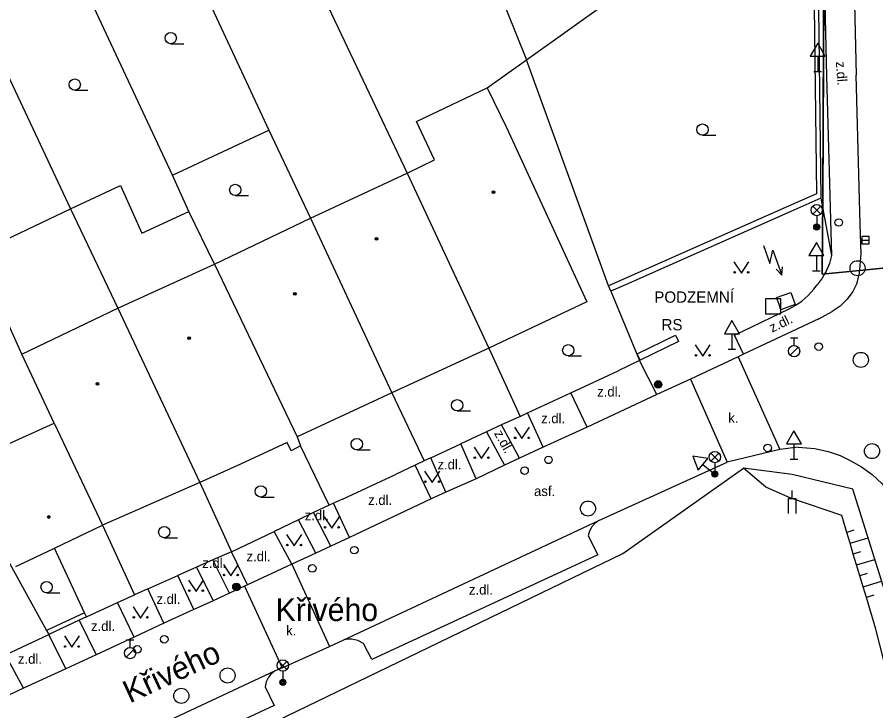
# Model space of a CAD drawing. Extents: x -598233 to -596890, y -1157848 to -1156431.
# Drawn here: x -598078.4 to -598021.4, y -1157106.7 to -1157060.7 of the extents above; entities that cross this region are included whole.
import ezdxf

# ---------------------------------------------------------------- set-up
doc = ezdxf.new("R2010")
doc.units = 0
for name, color, linetype in [('Level 10', 7, 'Continuous'), ('Level 11', 7, 'Continuous'), ('Level 14', 7, 'Continuous'), ('Level 15', 7, 'Continuous'), ('Level 24', 7, 'Continuous'), ('Level 25', 7, 'Continuous'), ('Level 26', 7, 'Continuous'), ('Level 27', 7, 'Continuous'), ('Level 28', 7, 'Continuous'), ('Level 33', 7, 'Continuous'), ('Level 34', 7, 'Continuous'), ('Level 36', 7, 'Continuous'), ('Level 38', 7, 'Continuous'), ('Level 39', 7, 'Continuous'), ('Level 40', 7, 'Continuous'), ('Level 41', 7, 'Continuous'), ('Level 49', 7, 'Continuous'), ('Level 5', 7, 'Continuous'), ('Level 50', 7, 'Continuous'), ('Level 7', 7, 'Continuous'), ('Level 8', 7, 'Continuous'), ('Vrstva 54', 7, 'Continuous'), ('Vrstva 60', 7, 'Continuous')]:
    doc.layers.add(name, color=color, linetype=linetype)

msp = doc.modelspace()

# ---------------------------------------------------------------- linework, layer by layer
at = {"layer": 'Level 10'}
for points in [[(-598023.23, -1157043.6), (-598022.76, -1157064.57)], [(-598022.48, -1157074.47), (-598022.76, -1157064.57)], [(-598022.41, -1157076.43), (-598022.48, -1157074.47)], [(-598022.52, -1157077.71), (-598022.41, -1157076.43)], [(-598022.52, -1157077.71), (-598022.41, -1157076.43)], [(-598022.68, -1157078.35), (-598022.52, -1157077.71)], [(-598022.68, -1157078.35), (-598022.97, -1157078.92), (-598023.35, -1157079.44), (-598023.81, -1157079.89), (-598024.34, -1157080.26)], [(-598025.23, -1157080.74), (-598024.34, -1157080.26)], [(-598025.23, -1157080.74), (-598030.2199, -1157083.08)], [(-598030.58, -1157083.25), (-598033.74, -1157084.73)], [(-598030.2199, -1157083.08), (-598030.58, -1157083.25)], [(-598033.74, -1157084.73), (-598035.98, -1157085.76)], [(-598035.98, -1157085.76), (-598040.61, -1157087.93)], [(-598040.61, -1157087.93), (-598043.53, -1157089.25)], [(-598043.53, -1157089.25), (-598045.09, -1157089.98)], [(-598027.82, -1157089.4), (-598031.32, -1157090.24)], [(-598026.59, -1157089.25), (-598027.82, -1157089.4)], [(-598026.59, -1157089.25), (-598025.5, -1157089.33), (-598024.62, -1157089.53), (-598023.81, -1157089.79), (-598023.15, -1157090.13), (-598022.39, -1157090.55), (-598021.68, -1157091.06), (-598021.05, -1157091.65), (-598020.49, -1157092.32)], [(-598045.09, -1157089.98), (-598046.08, -1157090.45)], [(-598039.83, -1157094.11), (-598031.32, -1157090.24)], [(-598046.08, -1157090.45), (-598047.9699, -1157091.34)], [(-598047.9699, -1157091.34), (-598049.98, -1157092.24)], [(-598049.98, -1157092.24), (-598050.95, -1157092.68)], [(-598050.95, -1157092.68), (-598056.38, -1157095.23)], [(-598056.76, -1157102.02), (-598039.83, -1157094.11)], [(-598056.38, -1157095.23), (-598057.62, -1157095.81)], [(-598057.62, -1157095.81), (-598058.62, -1157096.27)], [(-598058.62, -1157096.27), (-598060.2, -1157097)], [(-598060.2, -1157097), (-598063.15, -1157098.38)], [(-598063.34, -1157098.46), (-598064.34, -1157098.93)], [(-598063.15, -1157098.38), (-598063.34, -1157098.46)], [(-598064.34, -1157098.93), (-598065.43, -1157099.44)], [(-598065.43, -1157099.44), (-598066.7, -1157100.01)], [(-598066.7, -1157100.01), (-598068.7, -1157100.92)], [(-598068.7, -1157100.92), (-598070.6599, -1157101.84)], [(-598070.6599, -1157101.84), (-598073.19, -1157103.03)], [(-598057.7, -1157102.46), (-598056.76, -1157102.02)], [(-598060.85, -1157103.88), (-598057.7, -1157102.46)], [(-598073.19, -1157103.03), (-598075.2, -1157103.95)], [(-598061.29, -1157104.07), (-598060.85, -1157103.88)], [(-598075.2, -1157103.95), (-598078.02, -1157105.24)], [(-598073.24, -1157109.65), (-598061.29, -1157104.07)], [(-598078.02, -1157105.24), (-598079.84, -1157106.1)]]:
    msp.add_lwpolyline(points, dxfattribs=at)
at = {"layer": 'Level 11'}
for points in [[(-598029.1599, -1157039.71), (-598027.87, -1157040.27), (-598026.67, -1157041.27), (-598025.83, -1157042.49), (-598025.38, -1157043.53), (-598025.19, -1157044.38), (-598024.71, -1157064.65)], [(-598029.1599, -1157039.71), (-598027.87, -1157040.27), (-598026.67, -1157041.27), (-598025.83, -1157042.49), (-598025.38, -1157043.53), (-598025.19, -1157044.38), (-598024.71, -1157064.65)], [(-598064.9099, -1157045.04), (-598052.54, -1157071.07)], [(-598071.09, -1157048.14), (-598061.73, -1157068.2199)], [(-598068.13, -1157071.2199), (-598077.39, -1157051.4)], [(-598083.78, -1157054.53), (-598074.89, -1157073.45)], [(-598044.64, -1157063.56), (-598039.23, -1157059.7199)], [(-598047.25, -1157065.4099), (-598044.64, -1157063.56)], [(-598024.71, -1157064.65), (-598024.39, -1157076.54)], [(-598068.13, -1157071.2199), (-598061.73, -1157068.2199)], [(-598061.73, -1157068.2199), (-598058.96, -1157074.07)], [(-598067.04, -1157073.61), (-598068.13, -1157071.2199)], [(-598074.89, -1157073.45), (-598071.57, -1157071.9), (-598070.17, -1157075.05), (-598067.04, -1157073.61)], [(-598025.09, -1157072.74), (-598024.39, -1157076.54)], [(-598025.09, -1157072.74), (-598024.39, -1157076.54)], [(-598078.12, -1157083.07), (-598081.13, -1157076.4099), (-598074.89, -1157073.45)], [(-598074.89, -1157073.45), (-598071.75, -1157080.04)], [(-598065.33, -1157077.12), (-598067.04, -1157073.61)], [(-598024.39, -1157076.54), (-598024.53, -1157077.07)], [(-598024.53, -1157077.07), (-598024.74, -1157077.57)], [(-598024.74, -1157077.57), (-598024.81, -1157077.69), (-598025.01, -1157078.04), (-598025.34, -1157078.48)], [(-598024.74, -1157077.57), (-598024.81, -1157077.69), (-598025.01, -1157078.04), (-598025.34, -1157078.48)], [(-598030.2199, -1157083.08), (-598030.82, -1157081.81), (-598027.2, -1157080.07), (-598026.75, -1157079.82), (-598026.33, -1157079.54), (-598025.93, -1157079.18), (-598025.56, -1157078.78), (-598025.34, -1157078.48)], [(-598030.58, -1157083.25), (-598027.82, -1157089.4)], [(-598035.98, -1157085.76), (-598037.12, -1157083.51)], [(-598033.74, -1157084.73), (-598031.32, -1157090.24)], [(-598040.61, -1157087.93), (-598041.69, -1157085.64)], [(-598043.53, -1157089.25), (-598044.57, -1157086.98)], [(-598045.09, -1157089.98), (-598046.28, -1157087.77)], [(-598047.28, -1157088.24), (-598046.08, -1157090.45)], [(-598047.9699, -1157091.34), (-598048.99, -1157089.03)], [(-598049.98, -1157092.24), (-598050.99, -1157089.96)], [(-598117.4, -1157134.54), (-598038.23, -1157096.29), (-598030.2199, -1157090.63)], [(-598050.95, -1157092.68), (-598052.02, -1157090.44)], [(-598022.98, -1157092.03), (-598026.99, -1157091.05), (-598030.2199, -1157090.63)], [(-598016.79, -1157115.02), (-598020.01, -1157101.48), (-598022.98, -1157092.03)], [(-598056.38, -1157095.23), (-598057.44, -1157092.9699)], [(-598057.62, -1157095.81), (-598058.76, -1157093.59)], [(-598058.62, -1157096.27), (-598059.76, -1157094.07)], [(-598039.83, -1157094.11), (-598040.09, -1157094.31), (-598040.29, -1157094.54), (-598040.44, -1157094.82), (-598040.53, -1157095.13), (-598039.89, -1157096.39), (-598054.89, -1157103.34), (-598055.44, -1157102.27), (-598055.83, -1157102.07), (-598056.2199, -1157101.99), (-598056.49, -1157101.98), (-598056.76, -1157102.02)], [(-598060.2, -1157097), (-598061.38, -1157094.84)], [(-598073.96, -1157100.24), (-598075.96, -1157095.94)], [(-598063.15, -1157098.38), (-598064.21, -1157096.19)], [(-598064.34, -1157098.93), (-598065.44, -1157096.73)], [(-598060.2, -1157097), (-598057.7, -1157102.46)], [(-598066.54, -1157097.21), (-598065.43, -1157099.44)], [(-598066.7, -1157100.01), (-598067.76, -1157097.75)], [(-598068.7, -1157100.92), (-598069.77, -1157098.64)], [(-598063.34, -1157098.46), (-598060.85, -1157103.88)], [(-598070.6599, -1157101.84), (-598071.77, -1157099.55)], [(-598074.31, -1157100.73), (-598073.19, -1157103.03)], [(-598075.2, -1157103.95), (-598076.34, -1157101.68)], [(-598078.02, -1157105.24), (-598079.2, -1157103.02)], [(-598061.29, -1157104.07), (-598061.6, -1157104.3), (-598061.76, -1157104.51), (-598061.9099, -1157104.82), (-598061.9699, -1157105.14), (-598061.38, -1157106.39), (-598071.35, -1157111.02), (-598071.92, -1157109.84), (-598072.24, -1157109.6599), (-598072.59, -1157109.57), (-598072.85, -1157109.56), (-598073.24, -1157109.65)]]:
    msp.add_lwpolyline(points, dxfattribs=at)
at = {"layer": 'Level 14'}
msp.add_lwpolyline([(-598016.79, -1157115.02), (-598017.94, -1157115.01), (-598021.44, -1157101.31), (-598022.07, -1157099.21), (-598022.29, -1157098.5), (-598022.51, -1157097.78), (-598022.7199, -1157097.06), (-598022.94, -1157096.34), (-598023.15, -1157095.62), (-598023.37, -1157094.9099), (-598023.71, -1157093.78), (-598027.09, -1157092.63), (-598028.75, -1157091.89), (-598030.2199, -1157090.63)], dxfattribs=at)
at = {"layer": 'Level 15'}
for points in [[(-598022.9, -1157094.76), (-598023.37, -1157094.9099)], [(-598023.15, -1157095.62), (-598021.96, -1157095.26)], [(-598022.46, -1157096.2), (-598022.94, -1157096.34)], [(-598022.7199, -1157097.06), (-598021.51, -1157096.7)], [(-598022.02, -1157097.63), (-598022.51, -1157097.78)], [(-598022.29, -1157098.5), (-598021.06, -1157098.13)], [(-598021.58, -1157099.07), (-598022.07, -1157099.21)]]:
    msp.add_lwpolyline(points, dxfattribs=at)
at = {"layer": 'Level 24'}
for points in [[(-598028.03, -1157079.33), (-598027.09, -1157078.99)], [(-598027.89, -1157079.73), (-598028.03, -1157079.33)], [(-598027.09, -1157078.99), (-598026.81, -1157079.79)], [(-598027.75, -1157080.13), (-598027.89, -1157079.73)], [(-598026.81, -1157079.79), (-598027.75, -1157080.13)], [(-598037.29, -1157083.05), (-598034.74, -1157081.83), (-598034.55, -1157082.24), (-598037.08, -1157083.4699), (-598037.29, -1157083.05)]]:
    msp.add_lwpolyline(points, dxfattribs=at)
at = {"layer": 'Level 25'}
for centre, radius in [((-598035.89, -1157085.09), 0.25), ((-598035.89, -1157085.09), 0.2), ((-598035.89, -1157085.09), 0.15), ((-598035.89, -1157085.09), 0.1), ((-598035.89, -1157085.09), 0.05), ((-598063.88, -1157098.52), 0.25), ((-598063.88, -1157098.52), 0.2), ((-598063.88, -1157098.52), 0.15), ((-598063.88, -1157098.52), 0.1), ((-598063.88, -1157098.52), 0.05)]:
    msp.add_circle(centre, radius, dxfattribs=at)
at = {"layer": 'Level 26'}
msp.add_lwpolyline([(-598028.76, -1157080.4099), (-598027.76, -1157080.4099), (-598027.76, -1157079.4099), (-598028.76, -1157079.4099)], close=True, dxfattribs=at)
at = {"layer": 'Level 27'}
msp.add_line((-598022.38, -1157075.52), (-598021.88, -1157075.52), dxfattribs=at)
msp.add_lwpolyline([(-598022.38, -1157075.77), (-598021.88, -1157075.77), (-598021.88, -1157075.27), (-598022.38, -1157075.27)], close=True, dxfattribs=at)
for centre in [(-598022.66, -1157077.38), (-598022.44, -1157083.46), (-598021.7, -1157089.51), (-598040.55, -1157093.32), (-598064.4699, -1157104.39), (-598067.54, -1157105.74)]:
    msp.add_circle(centre, 0.5, dxfattribs=at)
at = {"layer": 'Level 28'}
for p, q in [((-598027.12, -1157082.005), (-598026.62, -1157082.005)), ((-598026.87, -1157082.505), (-598026.87, -1157082.005)), ((-598027.128, -1157083.152), (-598026.598, -1157082.622)), ((-598071.19, -1157102.025), (-598070.69, -1157102.025)), ((-598070.94, -1157102.525), (-598070.94, -1157102.025)), ((-598071.198, -1157103.172), (-598070.668, -1157102.642))]:
    msp.add_line(p, q, dxfattribs=at)
for centre, radius in [((-598023.91, -1157074.35), 0.25), ((-598026.87, -1157082.88), 0.375), ((-598025.24, -1157082.58), 0.25), ((-598028.62, -1157089.3), 0.25), ((-598043.17, -1157090.09), 0.25), ((-598044.76, -1157090.8), 0.25), ((-598056.06, -1157096.08), 0.25), ((-598058.85, -1157097.29), 0.25), ((-598068.67, -1157101.99), 0.25), ((-598070.94, -1157102.9), 0.375), ((-598070.46, -1157102.6599), 0.25)]:
    msp.add_circle(centre, radius, dxfattribs=at)
at = {"layer": 'Level 33'}
for p, q in [((-598025.635, -1157073.79), (-598025.105, -1157073.26)), ((-598025.635, -1157073.26), (-598025.105, -1157073.79)), ((-598025.37, -1157073.9), (-598025.37, -1157074.65)), ((-598032.395, -1157090.17), (-598031.865, -1157089.64)), ((-598032.395, -1157089.64), (-598031.865, -1157090.17)), ((-598032.13, -1157090.28), (-598032.13, -1157091.03)), ((-598061.065, -1157103.99), (-598060.535, -1157103.46)), ((-598061.065, -1157103.46), (-598060.535, -1157103.99)), ((-598060.8, -1157104.1), (-598060.8, -1157104.85))]:
    msp.add_line(p, q, dxfattribs=at)
for centre, radius in [((-598025.37, -1157073.525), 0.375), ((-598025.37, -1157074.65), 0.2), ((-598025.37, -1157074.65), 0.1445), ((-598025.37, -1157074.65), 0.0876), ((-598032.13, -1157089.905), 0.375), ((-598032.13, -1157091.03), 0.2), ((-598032.13, -1157091.03), 0.1445), ((-598032.13, -1157091.03), 0.0876), ((-598060.8, -1157103.725), 0.375), ((-598060.8, -1157104.85), 0.2), ((-598060.8, -1157104.85), 0.1445), ((-598060.8, -1157104.85), 0.0876)]:
    msp.add_circle(centre, radius, dxfattribs=at)
at = {"layer": 'Level 34'}
for p, q in [((-598025.3, -1157063.322), (-598025.3, -1157064.34)), ((-598025.55, -1157064.34), (-598025.05, -1157064.34)), ((-598025.39, -1157076.542), (-598025.39, -1157077.56)), ((-598025.64, -1157077.56), (-598025.14, -1157077.56)), ((-598031, -1157081.722), (-598031, -1157082.74)), ((-598031.25, -1157082.74), (-598030.75, -1157082.74)), ((-598026.88, -1157089.022), (-598026.88, -1157090.04)), ((-598027.13, -1157090.04), (-598026.63, -1157090.04)), ((-598032.9208, -1157090.3889), (-598032.13, -1157091.03)), ((-598032.2874, -1157091.2242), (-598031.9726, -1157090.8358))]:
    msp.add_line(p, q, dxfattribs=at)
for points in [[(-598025.8, -1157063.322), (-598024.8, -1157063.322), (-598025.3, -1157062.456)], [(-598025.89, -1157076.542), (-598024.89, -1157076.542), (-598025.39, -1157075.676)], [(-598031.5, -1157081.722), (-598030.5, -1157081.722), (-598031, -1157080.856)], [(-598027.38, -1157089.022), (-598026.38, -1157089.022), (-598026.88, -1157088.156)], [(-598033.2357, -1157090.7773), (-598032.6059, -1157090.0005), (-598033.5935, -1157089.8436)]]:
    msp.add_lwpolyline(points, close=True, dxfattribs=at)
at = {"layer": 'Level 36'}
for p, q in [((-598068.24, -1157062.495), (-598067.365, -1157062.495)), ((-598074.61, -1157065.575), (-598073.735, -1157065.575)), ((-598032.95, -1157068.565), (-598032.075, -1157068.565)), ((-598063.96, -1157072.565), (-598063.085, -1157072.565)), ((-598041.86, -1157083.195), (-598040.985, -1157083.195)), ((-598049.23, -1157086.845), (-598048.355, -1157086.845)), ((-598055.89, -1157089.425), (-598055.015, -1157089.425)), ((-598062.26, -1157092.555), (-598061.385, -1157092.555)), ((-598068.67, -1157095.255), (-598067.795, -1157095.255)), ((-598076.48, -1157098.905), (-598075.605, -1157098.905))]:
    msp.add_line(p, q, dxfattribs=at)
for points in [[(-598028.91, -1157075.88), (-598028.4895, -1157077.0571), (-598028.2709, -1157076.1826), (-598027.6822, -1157077.8306)], [(-598030.87, -1157076.95), (-598030.37, -1157077.7), (-598029.87, -1157076.95)], [(-598028.0529, -1157077.4438), (-598027.6822, -1157077.8306), (-598027.6404, -1157077.2964)], [(-598033.43, -1157082.46), (-598032.93, -1157083.21), (-598032.43, -1157082.46)], [(-598045.43, -1157087.93), (-598044.93, -1157088.68), (-598044.43, -1157087.93)], [(-598048.11, -1157089.25), (-598047.61, -1157090), (-598047.11, -1157089.25)], [(-598051.39, -1157090.84), (-598050.89, -1157091.59), (-598050.39, -1157090.84)], [(-598058.05, -1157093.86), (-598057.55, -1157094.61), (-598057.05, -1157093.86)], [(-598060.55, -1157095.04), (-598060.05, -1157095.79), (-598059.55, -1157095.04)], [(-598064.75, -1157097.03), (-598064.25, -1157097.78), (-598063.75, -1157097.03)], [(-598067.06, -1157098.06), (-598066.56, -1157098.81), (-598066.06, -1157098.06)], [(-598070.74, -1157099.83), (-598070.24, -1157100.58), (-598069.74, -1157099.83)], [(-598075.3, -1157101.77), (-598074.8, -1157102.52), (-598074.3, -1157101.77)]]:
    msp.add_lwpolyline(points, dxfattribs=at)
for centre, radius in [((-598068.2401, -1157062.1199), 0.375), ((-598074.6101, -1157065.1999), 0.375), ((-598032.9501, -1157068.1899), 0.375), ((-598063.9601, -1157072.1899), 0.375), ((-598030.8202, -1157077.6498), 0.05), ((-598029.9208, -1157077.6498), 0.05), ((-598041.8601, -1157082.8199), 0.375), ((-598033.3802, -1157083.1598), 0.05), ((-598032.4808, -1157083.1598), 0.05), ((-598049.2301, -1157086.4699), 0.375), ((-598055.8901, -1157089.0499), 0.375), ((-598045.3802, -1157088.6298), 0.05), ((-598044.4808, -1157088.6298), 0.05), ((-598048.0602, -1157089.9498), 0.05), ((-598047.1608, -1157089.9498), 0.05), ((-598062.2601, -1157092.1799), 0.375), ((-598051.3402, -1157091.5398), 0.05), ((-598050.4408, -1157091.5398), 0.05), ((-598068.6701, -1157094.8799), 0.375), ((-598058.0002, -1157094.5598), 0.05), ((-598057.1008, -1157094.5598), 0.05), ((-598060.5002, -1157095.7398), 0.05), ((-598059.6008, -1157095.7398), 0.05), ((-598076.4801, -1157098.5299), 0.375), ((-598064.7002, -1157097.7298), 0.05), ((-598063.8008, -1157097.7298), 0.05), ((-598067.0102, -1157098.7598), 0.05), ((-598066.1108, -1157098.7598), 0.05), ((-598070.6902, -1157100.5298), 0.05), ((-598069.7908, -1157100.5298), 0.05), ((-598075.2502, -1157102.4698), 0.05), ((-598074.3508, -1157102.4698), 0.05)]:
    msp.add_circle(centre, radius, dxfattribs=at)
at = {"layer": 'Level 38'}
msp.add_line((-598027, -1157092.65), (-598027, -1157092.12), dxfattribs=at)
msp.add_lwpolyline([(-598027.25, -1157093.65), (-598027.25, -1157092.65), (-598026.75, -1157092.65), (-598026.75, -1157093.65)], dxfattribs=at)
at = {"layer": 'Level 39'}
for centre, radius in [((-598046.82, -1157072.34), 0.09), ((-598046.82, -1157072.34), 0.0398), ((-598054.58, -1157075.43), 0.09), ((-598054.58, -1157075.43), 0.0398), ((-598060, -1157079.08), 0.09), ((-598060, -1157079.08), 0.0398), ((-598067.01, -1157082.02), 0.09), ((-598067.01, -1157082.02), 0.0398), ((-598073.11, -1157085.04), 0.09), ((-598073.11, -1157085.04), 0.0398), ((-598076.34, -1157093.88), 0.09), ((-598076.34, -1157093.88), 0.0398)]:
    msp.add_circle(centre, radius, dxfattribs=at)
at = {"layer": 'Level 5'}
for points in [[(-598051.92, -1157067.65), (-598047.25, -1157065.4099)], [(-598047.25, -1157065.4099), (-598045.96, -1157068.04)], [(-598050.73, -1157070.2), (-598051.92, -1157067.65)], [(-598045.96, -1157068.04), (-598040.63, -1157079.61)], [(-598052.54, -1157071.07), (-598050.73, -1157070.2)], [(-598058.96, -1157074.07), (-598052.54, -1157071.07)], [(-598052.54, -1157071.07), (-598047.13, -1157082.68)], [(-598065.33, -1157077.12), (-598058.96, -1157074.07)], [(-598058.96, -1157074.07), (-598053.57, -1157085.64)], [(-598071.75, -1157080.04), (-598065.33, -1157077.12)], [(-598065.33, -1157077.12), (-598059.86, -1157088.56)], [(-598040.63, -1157079.61), (-598047.13, -1157082.68)], [(-598078.12, -1157083.07), (-598071.75, -1157080.04)], [(-598071.75, -1157080.04), (-598066.31, -1157091.6)], [(-598047.13, -1157082.68), (-598053.57, -1157085.64)], [(-598075.98, -1157087.6599), (-598078.12, -1157083.07)], [(-598053.57, -1157085.64), (-598059.86, -1157088.56)], [(-598082.34, -1157090.54), (-598075.98, -1157087.6599)], [(-598075.98, -1157087.6599), (-598072.76, -1157094.42)], [(-598060.51, -1157088.93), (-598063.61, -1157090.38)], [(-598060.24, -1157089.49), (-598060.51, -1157088.93)], [(-598059.86, -1157088.56), (-598059.63, -1157089.1599)], [(-598059.63, -1157089.1599), (-598060.24, -1157089.49)], [(-598063.61, -1157090.38), (-598066.31, -1157091.6)], [(-598066.31, -1157091.6), (-598072.76, -1157094.42)], [(-598075.96, -1157095.94), (-598072.76, -1157094.42)], [(-598078.52, -1157097.1599), (-598075.96, -1157095.94)]]:
    msp.add_lwpolyline(points, dxfattribs=at)
at = {"layer": 'Level 7'}
for points in [[(-598054.01, -1157040.25), (-598044.64, -1157063.56)], [(-598025.74, -1157044.07), (-598025.39, -1157072.44)], [(-598025.44, -1157043.99), (-598025.09, -1157072.74)], [(-598025.44, -1157043.99), (-598025.09, -1157072.74)], [(-598039.19, -1157078.54), (-598044.64, -1157063.56)], [(-598025.39, -1157072.44), (-598027.25, -1157073.27), (-598038.23, -1157078.12), (-598039.19, -1157078.54)], [(-598025.09, -1157072.74), (-598027.09, -1157073.63), (-598038.07, -1157078.48), (-598039.04, -1157078.9)], [(-598039.04, -1157078.9), (-598039.19, -1157078.54)], [(-598039.04, -1157078.9), (-598037.12, -1157083.51)], [(-598047.13, -1157082.68), (-598045.06, -1157087.21)], [(-598037.12, -1157083.51), (-598038.54, -1157084.18)], [(-598053.57, -1157085.64), (-598051.42, -1157090.1599)], [(-598045.06, -1157087.21), (-598046.28, -1157087.77)], [(-598046.28, -1157087.77), (-598047.28, -1157088.24)], [(-598047.28, -1157088.24), (-598048.99, -1157089.03)], [(-598057.73, -1157093.1), (-598059.63, -1157089.1599)], [(-598051.42, -1157090.1599), (-598052.02, -1157090.44)], [(-598050.99, -1157089.96), (-598051.42, -1157090.1599)], [(-598052.02, -1157090.44), (-598053.33, -1157091.05)], [(-598066.31, -1157091.6), (-598064.21, -1157096.19)], [(-598057.73, -1157093.1), (-598058.76, -1157093.59)], [(-598057.44, -1157092.9699), (-598057.73, -1157093.1)], [(-598056.84, -1157092.69), (-598057.44, -1157092.9699)], [(-598058.76, -1157093.59), (-598059.76, -1157094.07)], [(-598059.76, -1157094.07), (-598061.38, -1157094.84)], [(-598072.76, -1157094.42), (-598070.65, -1157099.03)], [(-598064.21, -1157096.19), (-598065.44, -1157096.73)], [(-598079.05, -1157096.75), (-598076.49, -1157101.4099)], [(-598065.44, -1157096.73), (-598066.54, -1157097.21)], [(-598066.54, -1157097.21), (-598067.76, -1157097.75)], [(-598069.77, -1157098.64), (-598070.65, -1157099.03)], [(-598073.96, -1157100.24), (-598076.49, -1157101.4099)], [(-598073.84, -1157100.51), (-598073.96, -1157100.24)], [(-598074.31, -1157100.73), (-598076.34, -1157101.68)], [(-598073.84, -1157100.51), (-598074.31, -1157100.73)], [(-598076.49, -1157101.4099), (-598076.34, -1157101.68)]]:
    msp.add_lwpolyline(points, dxfattribs=at)
at = {"layer": 'Level 8'}
for points in [[(-598041.69, -1157085.64), (-598038.54, -1157084.18)], [(-598045.06, -1157087.21), (-598044.57, -1157086.98), (-598041.69, -1157085.64)], [(-598050.99, -1157089.96), (-598048.99, -1157089.03)], [(-598056.84, -1157092.69), (-598053.33, -1157091.05)], [(-598064.21, -1157096.19), (-598061.38, -1157094.84)], [(-598069.77, -1157098.64), (-598067.76, -1157097.75)], [(-598073.84, -1157100.51), (-598071.77, -1157099.55), (-598070.65, -1157099.03)], [(-598079.2, -1157103.02), (-598076.34, -1157101.68)]]:
    msp.add_lwpolyline(points, dxfattribs=at)
at = {"layer": 'Vrstva 54'}
for p, q in [((-598024.89, -1157056.73), (-598024.97, -1157072.7)), ((-598024.97, -1157072.7), (-598025, -1157077.78)), ((-598022.29, -1157077.5), (-598016.22, -1157076.88)), ((-598025, -1157077.78), (-598022.29, -1157077.5))]:
    msp.add_line(p, q, dxfattribs=at)
at = {"layer": 'Vrstva 60'}
for points in [[(-598027.67, -1156974.53), (-598026.95, -1156998.63), (-598025.75, -1157019.06), (-598025.81, -1157024.28), (-598025.87, -1157029.09), (-598026, -1157039.23), (-598025.69, -1157044.06), (-598024.89, -1157056.73), (-598024.97, -1157072.7), (-598025, -1157077.78), (-598022.29, -1157077.5), (-598016.22, -1157076.88)], [(-598016.22, -1157076.88), (-598022.29, -1157077.5), (-598025, -1157077.78), (-598024.97, -1157072.7), (-598024.89, -1157056.73), (-598025.69, -1157044.06), (-598026, -1157039.23), (-598025.87, -1157029.09), (-598025.81, -1157024.28), (-598025.75, -1157019.06), (-598026.95, -1156998.63), (-598027.67, -1156974.53)]]:
    msp.add_lwpolyline(points, dxfattribs=at)

# ---------------------------------------------------------------- texts
at = {"layer": 'Level 40'}
for rotation, p in [(274.19953, (-598024.1, -1157063.69)), (26, (-598028.33, -1157081.6599)), (299, (-598046.8, -1157088.33))]:
    msp.add_text('z.dl.', height=0.65, rotation=rotation, dxfattribs=at).set_placement(p)
for s, p in [('z.dl.', (-598039.94, -1157085.89)), ('z.dl.', (-598043.6599, -1157087.6599)), ('k. ', (-598031.24, -1157087.63)), ('z.dl.', (-598050.54, -1157090.7199)), ('asf.', (-598044.13, -1157092.49)), ('z.dl.', (-598055.14, -1157093.08)), ('z.dl.', (-598059.35, -1157094.1)), ('z.dl.', (-598063.21, -1157096.81)), ('z.dl.', (-598066.15, -1157097.26)), ('z.dl.', (-598048.45, -1157099.02)), ('z.dl.', (-598069.19, -1157099.65)), ('z.dl.', (-598073.53, -1157101.44)), ('k. ', (-598060.58, -1157101.73)), ('z.dl.', (-598078.38, -1157103.61))]:
    msp.add_text(s, height=0.65, dxfattribs=at).set_placement(p)
at = {"layer": 'Level 41'}
for s, p in [('PODZEMNÍ', (-598036.15, -1157079.67)), ('RS', (-598035.67, -1157081.5))]:
    msp.add_text(s, height=0.75, dxfattribs=at).set_placement(p)
at = {"layer": 'Level 49'}
msp.add_text('Křivého', height=1.5, dxfattribs=at).set_placement((-598061.28, -1157100.78))
at = {"layer": 'Level 50'}
msp.add_text('Křivého', height=1.5, rotation=24.85313, dxfattribs=at).set_placement((-598070.9635, -1157106.255))

doc.saveas('drawing.dxf')
